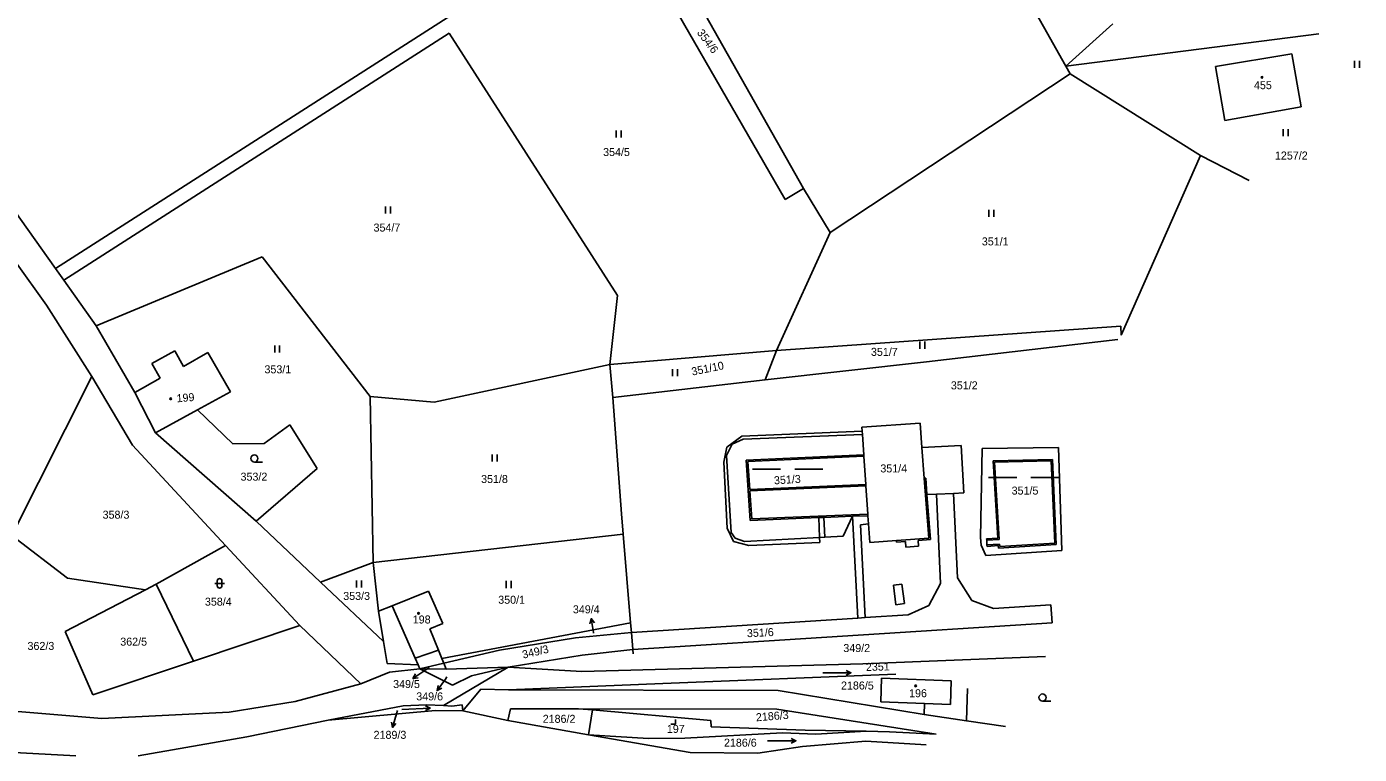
# Model space of a CAD drawing. Extents: x -717507 to -715515, y -957700 to -954941.
# Drawn here: x -716853.4 to -716570.3, y -957421.8 to -957267.1 of the extents above; entities that cross this region are included whole.
import ezdxf

# ---------------------------------------------------------------- set-up
doc = ezdxf.new("R2010")
doc.units = 0
for name, color, linetype in [('Hranice parcel', 7, 'Continuous'), ('Parcelní čísla', 7, 'Continuous'), ('Pop  PČ popisy', 7, 'Continuous'), ('Vnitřní kresba', 7, 'Continuous'), ('Značky budov', 7, 'Continuous'), ('Značky kultur', 7, 'Continuous')]:
    doc.layers.add(name, color=color, linetype=linetype)

msp = doc.modelspace()

# ---------------------------------------------------------------- linework, layer by layer
at = {"layer": 'Hranice parcel'}
for points in [[(-716692.24, -957303.82), (-716727.45, -957242.7)], [(-716688.33, -957301.5), (-716720.49, -957244.6)], [(-716847.23, -957318.53), (-716754.18, -957258.88)], [(-716642.15, -957258.58), (-716632.66, -957275.53)], [(-716845.5, -957320.98), (-716763.64, -957268.51)], [(-716763.64, -957268.51), (-716727.89, -957324.24)], [(-716632.66, -957275.53), (-716578.87, -957268.62)], [(-716600.84, -957275.6), (-716584.64, -957272.89)], [(-716584.64, -957272.89), (-716582.63, -957284.18)], [(-716632.66, -957275.53), (-716631.7, -957277.17)], [(-716600.84, -957275.6), (-716598.86, -957287.07)], [(-716682.72, -957310.9), (-716631.7, -957277.17)], [(-716604, -957294.53), (-716631.7, -957277.17)], [(-716598.86, -957287.07), (-716582.63, -957284.18)], [(-716604, -957294.53), (-716620.88, -957332.71)], [(-716604, -957294.53), (-716593.73, -957299.79)], [(-716861.8, -957298.02), (-716847.23, -957318.53)], [(-716692.24, -957303.82), (-716688.33, -957301.5)], [(-716682.72, -957310.9), (-716688.33, -957301.5)], [(-716862.39, -957307.87), (-716849.15, -957326.32)], [(-716682.72, -957310.9), (-716694.08, -957335.92)], [(-716847.23, -957318.53), (-716845.5, -957320.98)], [(-716838.58, -957330.73), (-716803.37, -957316.02)], [(-716803.37, -957316.02), (-716780.43, -957345.74)], [(-716845.5, -957320.98), (-716838.58, -957330.73)], [(-716839.53, -957341.5), (-716849.15, -957326.32)], [(-716727.89, -957324.24), (-716729.52, -957338.9)], [(-716838.58, -957330.73), (-716830.36, -957344.86)], [(-716620.97, -957330.74), (-716694.08, -957335.92)], [(-716620.97, -957330.74), (-716620.88, -957332.71)], [(-716621.61, -957333.63), (-716662.22, -957338.34)], [(-716826.79, -957338.67), (-716821.88, -957335.98)], [(-716821.88, -957335.98), (-716820.05, -957339.31)], [(-716814.91, -957336.34), (-716820.05, -957339.31)], [(-716814.91, -957336.34), (-716810.07, -957344.71)], [(-716694.08, -957335.92), (-716729.52, -957338.9)], [(-716694.08, -957335.92), (-716696.48, -957342.2)], [(-716696.48, -957342.2), (-716662.22, -957338.34)], [(-716826.79, -957338.67), (-716824.99, -957341.81)], [(-716766.82, -957346.9), (-716729.52, -957338.9)], [(-716729.52, -957338.9), (-716728.85, -957345.91)], [(-716839.53, -957341.5), (-716856.48, -957375.24)], [(-716839.53, -957341.5), (-716830.86, -957356.08)], [(-716824.99, -957341.81), (-716830.36, -957344.86)], [(-716728.85, -957345.91), (-716696.48, -957342.2)], [(-716830.36, -957344.86), (-716826, -957353.41)], [(-716817.06, -957348.56), (-716810.07, -957344.71)], [(-716780.43, -957345.74), (-716766.82, -957346.9)], [(-716779.73, -957380.97), (-716780.43, -957345.74)], [(-716727.02, -957370.65), (-716728.85, -957345.91)], [(-716826, -957353.41), (-716817.06, -957348.56)], [(-716817.06, -957348.56), (-716809.6, -957355.75)], [(-716802.94, -957355.69), (-716797.45, -957351.72)], [(-716797.45, -957351.72), (-716791.66, -957361.05)], [(-716675.96, -957352.2), (-716663.6, -957351.36)], [(-716675.96, -957352.2), (-716675.9, -957353.07)], [(-716663.6, -957351.36), (-716663.2, -957356.58)], [(-716826, -957353.41), (-716804.64, -957372.24)], [(-716701.45, -957354.16), (-716704.66, -957356.47)], [(-716701.45, -957354.16), (-716675.9, -957353.07)], [(-716675.9, -957353.07), (-716675.85, -957353.76)], [(-716675.85, -957353.76), (-716675.56, -957358.11)], [(-716811.15, -957377.37), (-716830.86, -957356.08)], [(-716809.6, -957355.75), (-716802.94, -957355.69)], [(-716705.31, -957359.7), (-716704.66, -957356.47)], [(-716675.54, -957358.41), (-716675.56, -957358.11)], [(-716663.2, -957356.58), (-716654.9, -957356.1)], [(-716654.9, -957356.1), (-716654.32, -957366.22)], [(-716650.4, -957356.76), (-716650.77, -957375.69)], [(-716650.4, -957356.76), (-716634.2, -957356.53)], [(-716634.2, -957356.53), (-716633.5, -957378.47)], [(-716705.31, -957359.7), (-716704.58, -957373.68)], [(-716675.13, -957364.42), (-716675.54, -957358.41)], [(-716804.64, -957372.24), (-716791.66, -957361.05)], [(-716675.11, -957364.73), (-716675.13, -957364.42)], [(-716674.7, -957370.69), (-716675.11, -957364.73)], [(-716662.14, -957366.56), (-716660.13, -957366.47)], [(-716662.14, -957366.56), (-716661.4, -957376.12)], [(-716660.13, -957366.47), (-716656.48, -957366.31)], [(-716659.28, -957385.44), (-716660.13, -957366.47)], [(-716656.48, -957366.31), (-716654.32, -957366.22)], [(-716656.48, -957366.31), (-716655.63, -957384.23)], [(-716790.95, -957385.17), (-716804.64, -957372.24)], [(-716726.66, -957374.96), (-716727.02, -957370.65)], [(-716677.98, -957371.17), (-716679.9, -957375.43)], [(-716677.98, -957371.17), (-716674.68, -957371.04)], [(-716674.68, -957371.04), (-716674.7, -957370.69)], [(-716674.56, -957372.74), (-716674.68, -957371.04)], [(-716779.73, -957380.97), (-716726.66, -957374.96)], [(-716725.08, -957393.78), (-716726.66, -957374.96)], [(-716704.58, -957373.68), (-716703.23, -957376.55)], [(-716674.56, -957372.74), (-716674.29, -957376.75)], [(-716856.48, -957375.24), (-716844.68, -957384.3)], [(-716811.15, -957377.37), (-716825.86, -957385.61)], [(-716795.35, -957394.38), (-716811.15, -957377.37)], [(-716699.95, -957377.4), (-716703.23, -957376.55)], [(-716699.95, -957377.4), (-716684.91, -957376.75)], [(-716684.94, -957375.69), (-716683.8, -957375.63)], [(-716684.94, -957375.69), (-716684.91, -957376.75)], [(-716679.9, -957375.43), (-716683.8, -957375.63)], [(-716674.29, -957376.75), (-716668.6, -957376.35)], [(-716668.58, -957376.65), (-716668.6, -957376.35)], [(-716666.69, -957376.51), (-716668.58, -957376.65)], [(-716666.69, -957376.51), (-716666.6, -957377.71)], [(-716666.6, -957377.71), (-716663.91, -957377.51)], [(-716661.4, -957376.12), (-716663.99, -957376.31)], [(-716663.99, -957376.31), (-716663.91, -957377.51)], [(-716650.77, -957375.69), (-716650.63, -957377.28)], [(-716650.63, -957377.28), (-716649.62, -957379.48)], [(-716649.62, -957379.48), (-716633.5, -957378.47)], [(-716790.95, -957385.17), (-716779.73, -957380.97)], [(-716779.73, -957380.97), (-716778.62, -957391.31)], [(-716844.68, -957384.3), (-716828.12, -957386.77)], [(-716825.86, -957385.61), (-716828.12, -957386.77)], [(-716825.86, -957385.61), (-716817.91, -957401.96)], [(-716790.95, -957385.17), (-716777.58, -957397.81)], [(-716661.75, -957390.13), (-716659.28, -957385.44)], [(-716655.63, -957384.23), (-716652.61, -957389.08)], [(-716828.12, -957386.77), (-716845.19, -957395.62)], [(-716775.76, -957390.19), (-716768.03, -957387.1)], [(-716768.03, -957387.1), (-716764.98, -957393.96)], [(-716652.61, -957389.08), (-716647.98, -957390.77)], [(-716778.62, -957391.31), (-716775.76, -957390.19)], [(-716777.58, -957397.81), (-716778.62, -957391.31)], [(-716675.26, -957392.68), (-716666.15, -957392.11)], [(-716661.75, -957390.13), (-716666.15, -957392.11)], [(-716635.84, -957389.99), (-716647.98, -957390.77)], [(-716635.84, -957389.99), (-716635.55, -957393.8)], [(-716817.91, -957401.96), (-716795.35, -957394.38)], [(-716782.35, -957406.77), (-716795.35, -957394.38)], [(-716764.98, -957393.96), (-716767.7, -957395.09)], [(-716765.16, -957401.36), (-716725.08, -957393.78)], [(-716724.86, -957395.9), (-716725.08, -957393.78)], [(-716724.86, -957395.9), (-716676.85, -957392.82)], [(-716724.61, -957399.51), (-716635.55, -957393.8)], [(-716676.85, -957392.82), (-716675.26, -957392.68)], [(-716845.19, -957395.62), (-716839.27, -957409.1)], [(-716776.79, -957402.48), (-716777.58, -957397.81)], [(-716767.7, -957395.09), (-716765.87, -957399.65)], [(-716752.9, -957399.64), (-716736.78, -957397.03)], [(-716736.78, -957397.03), (-716724.86, -957395.9)], [(-716724.61, -957399.51), (-716724.86, -957395.9)], [(-716770.81, -957401.34), (-716765.87, -957399.65)], [(-716764.75, -957402.38), (-716752.9, -957399.64)], [(-716735.39, -957400.71), (-716724.61, -957399.51)], [(-716724.55, -957400.42), (-716724.61, -957399.51)], [(-716839.27, -957409.1), (-716817.91, -957401.96)], [(-716776.79, -957402.48), (-716770.18, -957402.73)], [(-716770.81, -957401.34), (-716770.18, -957402.73)], [(-716770.18, -957402.73), (-716769.83, -957403.56)], [(-716769.83, -957403.56), (-716764.75, -957402.38)], [(-716765.16, -957401.36), (-716764.75, -957402.38)], [(-716764.79, -957411.41), (-716751.1, -957403.23)], [(-716764.75, -957402.38), (-716764.26, -957403.68)], [(-716764.26, -957403.68), (-716751.1, -957403.23)], [(-716758.87, -957405.04), (-716751.1, -957403.23)], [(-716735.39, -957400.71), (-716751.1, -957403.23)], [(-716735.45, -957404.13), (-716751.1, -957403.23)], [(-716735.45, -957404.13), (-716675.75, -957402.52)], [(-716675.75, -957402.52), (-716636.98, -957400.99)], [(-716776.26, -957404.29), (-716782.35, -957406.77)], [(-716776.26, -957404.29), (-716769.83, -957403.56)], [(-716769.83, -957403.56), (-716762.89, -957407.03)], [(-716769.83, -957403.56), (-716764.26, -957403.68)], [(-716762.89, -957407.03), (-716758.87, -957405.04)], [(-716668.76, -957404.71), (-716718.26, -957406.71)], [(-716671.81, -957405.57), (-716671.94, -957410.6)], [(-716657, -957406.17), (-716671.81, -957405.57)], [(-716657, -957406.17), (-716657.13, -957411.2)], [(-716782.35, -957406.77), (-716796.33, -957410.55)], [(-716760.74, -957412.54), (-716756.87, -957407.9)], [(-716756.87, -957407.9), (-716750.99, -957408.06)], [(-716750.99, -957408.06), (-716718.26, -957406.71)], [(-716750.99, -957408.06), (-716693.75, -957408.22)], [(-716693.75, -957408.22), (-716662.73, -957413.31)], [(-716653.75, -957414.65), (-716653.51, -957407.75)], [(-716837.39, -957414.15), (-716875.71, -957410.97)], [(-716796.33, -957410.55), (-716810.36, -957412.81)], [(-716789.34, -957414.49), (-716773.38, -957411.48)], [(-716773.38, -957411.48), (-716768.44, -957411.25)], [(-716768.44, -957411.25), (-716764.79, -957411.41)], [(-716764.79, -957411.41), (-716763.08, -957411.49)], [(-716763.08, -957411.49), (-716760.85, -957411.24)], [(-716760.85, -957411.24), (-716760.74, -957412.54)], [(-716662.69, -957410.97), (-716671.94, -957410.6)], [(-716662.69, -957410.97), (-716662.73, -957413.31)], [(-716657.13, -957411.2), (-716662.69, -957410.97)], [(-716810.36, -957412.81), (-716837.39, -957414.15)], [(-716806.59, -957418.02), (-716789.34, -957414.49)], [(-716789.34, -957414.49), (-716766.53, -957412.45)], [(-716766.53, -957412.45), (-716760.74, -957412.54)], [(-716760.74, -957412.54), (-716751.15, -957414.55)], [(-716751.15, -957414.55), (-716750.58, -957412.1)], [(-716751.15, -957414.55), (-716734.03, -957417.6)], [(-716750.58, -957412.1), (-716736.18, -957412.11)], [(-716733.17, -957412.33), (-716736.18, -957412.11)], [(-716736.18, -957412.11), (-716693.99, -957412.14)], [(-716733.17, -957412.33), (-716734.03, -957417.6)], [(-716733.17, -957412.33), (-716708.01, -957414.58)], [(-716708.01, -957414.58), (-716707.97, -957415.92)], [(-716693.99, -957412.14), (-716660.16, -957417.49)], [(-716662.73, -957413.31), (-716653.75, -957414.65)], [(-716645.43, -957415.86), (-716653.75, -957414.65)], [(-716734.03, -957417.6), (-716721.25, -957418.42)], [(-716734.03, -957417.6), (-716712.41, -957421.34)], [(-716713.58, -957418.3), (-716692.8, -957417.21)], [(-716707.97, -957415.92), (-716687.99, -957416.59)], [(-716692.8, -957417.21), (-716685.71, -957417.46)], [(-716687.99, -957416.59), (-716675.08, -957416.82)], [(-716685.71, -957417.46), (-716675.08, -957416.82)], [(-716675.08, -957416.82), (-716670.11, -957416.95)], [(-716670.11, -957416.95), (-716660.16, -957417.49)], [(-716829.71, -957422.08), (-716806.59, -957418.02)], [(-716721.25, -957418.42), (-716713.58, -957418.3)], [(-716698.06, -957421.5), (-716688.54, -957420.07)], [(-716688.54, -957420.07), (-716675.11, -957418.98)], [(-716675.11, -957418.98), (-716662.27, -957419.71)], [(-716842.94, -957422.09), (-716865.2, -957420.88)], [(-716712.41, -957421.34), (-716698.06, -957421.5)]]:
    msp.add_lwpolyline(points, dxfattribs=at)
at = {"layer": 'Pop  PČ popisy'}
for points in [[(-716733.77, -957393.99), (-716733.43, -957392.92), (-716732.78, -957393.84)], [(-716732.98, -957395.89), (-716733.43, -957392.92)], [(-716732.96, -957396), (-716732.98, -957395.89)], [(-716767.88, -957403.33), (-716768.82, -957403.96)], [(-716768.82, -957403.96), (-716771.31, -957405.63)], [(-716770.2, -957405.49), (-716771.31, -957405.63), (-716770.76, -957404.66)], [(-716764.42, -957405.77), (-716766.17, -957408.21)], [(-716764.09, -957405.31), (-716764.42, -957405.77)], [(-716765.18, -957407.69), (-716766.17, -957408.21), (-716765.99, -957407.11)], [(-716774.83, -957413.17), (-716775.68, -957416.05)], [(-716774.62, -957412.45), (-716774.83, -957413.17)], [(-716774.92, -957415.23), (-716775.68, -957416.05), (-716775.87, -957414.95)]]:
    msp.add_lwpolyline(points, dxfattribs=at)
at = {"layer": 'Vnitřní kresba'}
for points in [[(-716622.66, -957266.55), (-716632.66, -957275.53)], [(-716701.19, -957354.77), (-716703.53, -957355.87)], [(-716675.85, -957353.76), (-716701.19, -957354.77)], [(-716703.53, -957355.87), (-716704.72, -957358.27)], [(-716700.54, -957359.22), (-716675.56, -957358.11)], [(-716663.2, -957356.58), (-716662.7, -957363.1)], [(-716704.72, -957358.27), (-716703.69, -957374.64)], [(-716699.65, -957372.06), (-716700.54, -957359.22)], [(-716675.54, -957358.41), (-716700.16, -957359.54)], [(-716700.16, -957359.54), (-716699.76, -957365.5)], [(-716648.09, -957359.4), (-716635.44, -957359.07)], [(-716648.09, -957359.4), (-716647.08, -957375.8)], [(-716647.78, -957359.68), (-716635.72, -957359.39)], [(-716646.77, -957376.08), (-716647.78, -957359.68)], [(-716635.72, -957359.39), (-716634.98, -957376.88)], [(-716635.44, -957359.07), (-716634.66, -957377.15)], [(-716662.7, -957363.1), (-716662.4, -957363.08)], [(-716662.7, -957363.1), (-716661.73, -957375.85)], [(-716662.14, -957366.56), (-716662.4, -957363.08)], [(-716699.76, -957365.5), (-716675.13, -957364.42)], [(-716699.74, -957365.79), (-716675.11, -957364.73)], [(-716699.74, -957365.79), (-716699.32, -957371.69)], [(-716699.65, -957372.06), (-716685.07, -957371.46)], [(-716699.32, -957371.69), (-716674.7, -957370.69)], [(-716685.07, -957371.46), (-716684.07, -957371.42)], [(-716685.07, -957371.46), (-716684.94, -957375.69)], [(-716677.98, -957371.17), (-716684.07, -957371.42)], [(-716684.07, -957371.42), (-716683.8, -957375.63)], [(-716677.98, -957371.17), (-716676.85, -957392.82)], [(-716703.69, -957374.64), (-716702.87, -957375.84)], [(-716676.23, -957372.96), (-716674.56, -957372.74)], [(-716676.23, -957372.96), (-716675.26, -957392.68)], [(-716702.87, -957375.84), (-716700.9, -957376.52)], [(-716700.9, -957376.52), (-716684.94, -957375.69)], [(-716661.73, -957375.85), (-716668.6, -957376.35)], [(-716649.48, -957375.95), (-716647.08, -957375.8)], [(-716649.45, -957376.26), (-716649.48, -957375.95)], [(-716649.45, -957376.26), (-716646.77, -957376.08)], [(-716649.39, -957377.25), (-716649.45, -957376.26)], [(-716649.39, -957377.25), (-716646.71, -957377.09)], [(-716649.37, -957377.56), (-716649.39, -957377.25)], [(-716646.99, -957377.41), (-716649.37, -957377.56)], [(-716646.96, -957377.92), (-716646.99, -957377.41)], [(-716646.96, -957377.92), (-716634.66, -957377.15)], [(-716646.71, -957377.09), (-716646.68, -957377.59)], [(-716646.68, -957377.59), (-716634.98, -957376.88)], [(-716667.49, -957385.61), (-716669.26, -957385.84)], [(-716669.26, -957385.84), (-716668.74, -957389.96)], [(-716667.49, -957385.61), (-716666.88, -957389.72)], [(-716770.81, -957401.34), (-716775.76, -957390.19)], [(-716666.88, -957389.72), (-716668.74, -957389.96)], [(-716765.87, -957399.65), (-716765.16, -957401.36)]]:
    msp.add_lwpolyline(points, dxfattribs=at)
at = {"layer": 'Značky budov'}
for centre in [(-716590.97, -957277.91), (-716822.79, -957346.2), (-716770.12, -957391.8), (-716664.52, -957407.21)]:
    msp.add_circle(centre, 0.175, dxfattribs=at)
at = {"layer": 'Značky kultur'}
for points in [[(-716571.33, -957275.91), (-716571.33, -957274.41)], [(-716570.29, -957275.91), (-716570.29, -957274.41)], [(-716728.14, -957290.67), (-716728.14, -957289.17)], [(-716727.1, -957290.67), (-716727.1, -957289.17)], [(-716586.47, -957290.39), (-716586.47, -957288.89)], [(-716585.43, -957290.39), (-716585.43, -957288.89)], [(-716777.13, -957306.81), (-716777.13, -957305.31)], [(-716776.09, -957306.81), (-716776.09, -957305.31)], [(-716648.99, -957307.53), (-716648.99, -957306.03)], [(-716647.95, -957307.53), (-716647.95, -957306.03)], [(-716800.67, -957336.36), (-716800.67, -957334.86)], [(-716799.63, -957336.36), (-716799.63, -957334.86)], [(-716663.66, -957335.56), (-716663.66, -957334.06)], [(-716662.62, -957335.56), (-716662.62, -957334.06)], [(-716716.16, -957341.4), (-716716.16, -957339.9)], [(-716715.12, -957341.4), (-716715.12, -957339.9)], [(-716754.47, -957359.54), (-716754.47, -957358.04)], [(-716753.43, -957359.54), (-716753.43, -957358.04)], [(-716804.99, -957359.64), (-716803.24, -957359.64)], [(-716699.22, -957361.13), (-716693.22, -957361.13)], [(-716690.22, -957361.13), (-716684.22, -957361.13)], [(-716649.04, -957362.93), (-716643.04, -957362.93)], [(-716640.04, -957362.93), (-716634.04, -957362.93)], [(-716813.37, -957385.42), (-716811.37, -957385.42)], [(-716812.87, -957385.92), (-716812.87, -957384.92)], [(-716811.87, -957384.92), (-716811.87, -957385.92)], [(-716783.27, -957386.33), (-716783.27, -957384.83)], [(-716782.23, -957386.33), (-716782.23, -957384.83)], [(-716751.5, -957386.41), (-716751.5, -957384.91)], [(-716750.46, -957386.41), (-716750.46, -957384.91)], [(-716684.27, -957404.41), (-716678.27, -957404.41)], [(-716679.27, -957403.91), (-716678.27, -957404.41), (-716679.27, -957404.91)], [(-716773.65, -957412.2), (-716767.65, -957411.92)], [(-716768.68, -957411.47), (-716767.65, -957411.92), (-716768.63, -957412.47)], [(-716637.59, -957410.43), (-716635.84, -957410.43)], [(-716716.57, -957415.32), (-716715.57, -957415.32), (-716715.57, -957414.32)], [(-716695.98, -957418.86), (-716689.98, -957418.86)], [(-716690.98, -957418.36), (-716689.98, -957418.86), (-716690.98, -957419.36)]]:
    msp.add_lwpolyline(points, dxfattribs=at)
for centre in [(-716804.99, -957358.89), (-716637.59, -957409.68)]:
    msp.add_circle(centre, 0.75, dxfattribs=at)
for centre, start, end in [((-716812.37, -957384.92), 0.101, 180.0014), ((-716812.37, -957385.92), 180.1024, 0.0029)]:
    msp.add_arc(centre, 0.5, start, end, dxfattribs=at)

# ---------------------------------------------------------------- texts
at = {"layer": 'Parcelní čísla'}
for s, rotation, p in [('354/6', 306.8024, (-716711.08, -957268.44)), ('351/10', 11.5001, (-716711.96, -957341.28)), ('199', 4.5, (-716821.45, -957346.96)), ('351/3', 3.4, (-716694.58, -957364.39)), ('351/6', 2.7, (-716700.33, -957396.87)), ('349/3', 13.3001, (-716747.88, -957401.44)), ('2351', 1.4, (-716675.08, -957404.04)), ('2186/3', 4.5, (-716698.39, -957414.74))]:
    msp.add_text(s, height=1.7, rotation=rotation, dxfattribs=at).set_placement(p)
for s, p in [('455', (-716592.68, -957280.41)), ('354/5', (-716730.92, -957294.62)), ('1257/2', (-716588.22, -957295.36)), ('354/7', (-716779.68, -957310.67)), ('351/1', (-716650.48, -957313.61)), ('351/7', (-716674.03, -957337.08)), ('353/1', (-716802.85, -957340.79)), ('351/2', (-716657.06, -957344.2)), ('351/4', (-716672.03, -957361.85)), ('353/2', (-716807.93, -957363.6)), ('351/8', (-716756.84, -957364.1)), ('351/5', (-716644.15, -957366.56)), ('358/3', (-716837.23, -957371.68)), ('358/4', (-716815.5, -957390.16)), ('353/3', (-716786.12, -957388.95)), ('350/1', (-716753.2, -957389.76)), ('349/4', (-716737.34, -957391.79)), ('198', (-716771.35, -957393.95)), ('362/3', (-716853.18, -957399.57)), ('362/5', (-716833.48, -957398.66)), ('349/2', (-716679.9, -957400.02)), ('349/5', (-716775.52, -957407.67)), ('2186/5', (-716680.39, -957407.98)), ('349/6', (-716770.61, -957410.29)), ('196', (-716665.93, -957409.62)), ('2186/2', (-716743.75, -957415.06)), ('2189/3', (-716779.67, -957418.46)), ('197', (-716717.38, -957417.2)), ('2186/6', (-716705.25, -957420.13))]:
    msp.add_text(s, height=1.7, dxfattribs=at).set_placement(p)

doc.saveas('drawing.dxf')
